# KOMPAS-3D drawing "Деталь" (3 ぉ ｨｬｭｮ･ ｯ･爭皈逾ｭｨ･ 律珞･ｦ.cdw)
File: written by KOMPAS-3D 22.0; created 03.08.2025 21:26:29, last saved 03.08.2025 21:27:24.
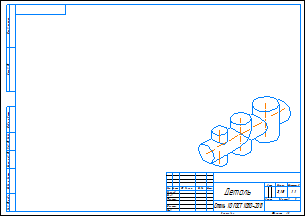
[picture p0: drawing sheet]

Sheet 1: A3, landscape

Document properties: Автор: user; Масса: 3.150427

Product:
- Body: Тело 1
    Масса: 1.974428
- Part/product: Деталь
    Масса: 3.150427

Title block, sheet 1: Наименование: Деталь; Материал: Сталь 10 ГОСТ 1050-2013; Масса: 3,15; Количество листов документа: 1; Форматы листов документа: A3; stored path: G:\08 03 воскресенье\2025 НГ Лаб работы\Лаб 3 Взаимное пересечение\03 Взаимное пересечение Чертеж.cdw

Views: Изометрия 2
Dimensions and other numbers on the sheet: 1; 1:1; 3,15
